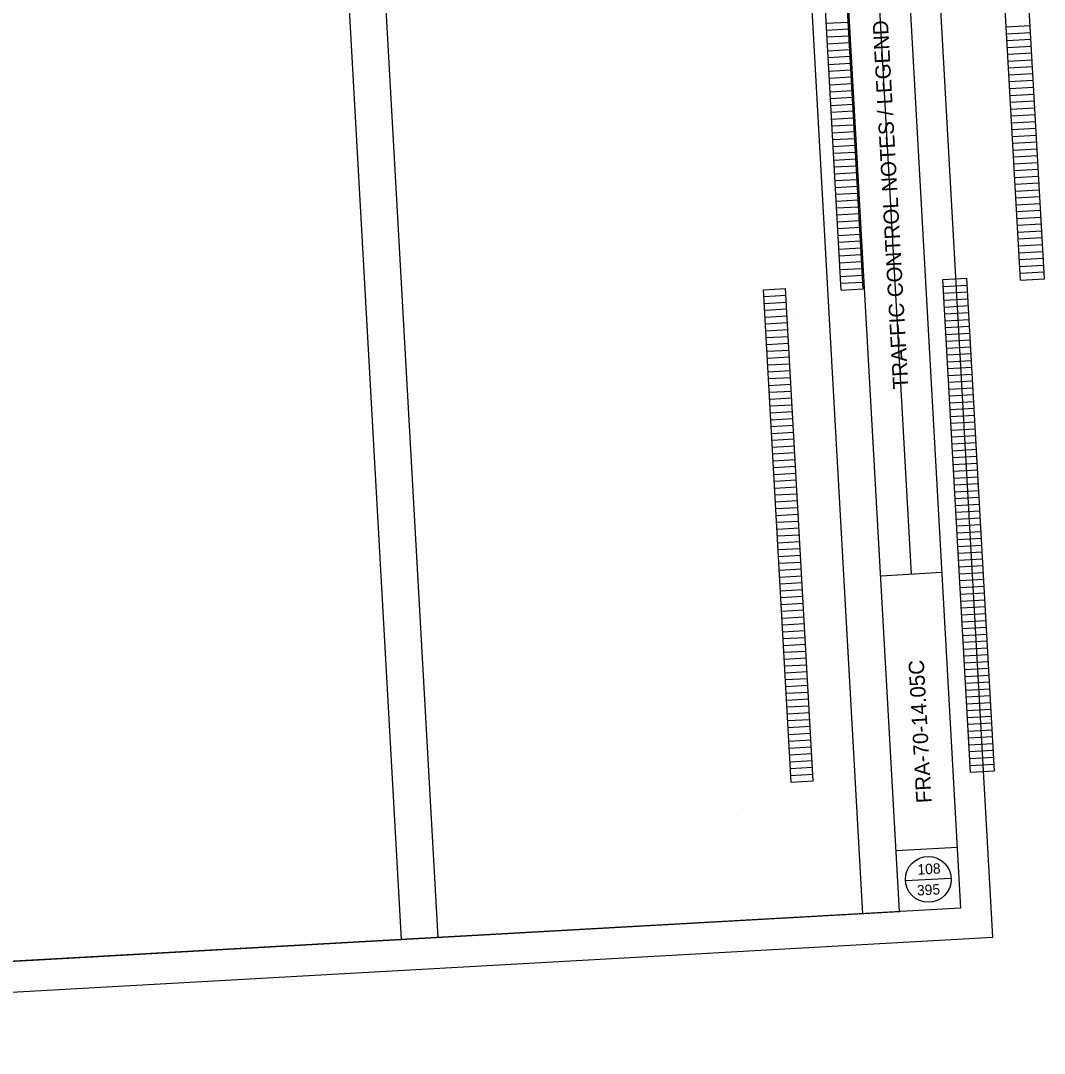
# Model space of a CAD drawing. Extents: x 1822280 to 1825263, y 710141 to 711534.
# Drawn here: x 1823244 to 1824081, y 710141 to 710986 of the extents above; entities that cross this region are included whole.
import ezdxf

# ---------------------------------------------------------------- set-up
doc = ezdxf.new("R2010")
doc.units = 0
for name, color, linetype in [('SC_Scratch1', 7, 'Continuous'), ('SH_Border', 7, 'Continuous'), ('SH_Cut_Line', 7, 'Continuous'), ('SH_Data', 7, 'Continuous'), ('SH_Text', 7, 'Continuous')]:
    doc.layers.add(name, color=color, linetype=linetype)

msp = doc.modelspace()

# ---------------------------------------------------------------- linework, layer by layer
at = {"layer": 'SC_Scratch1'}
for p, q in [((1823932.49, 710255.62), (1823860.99, 711532.17)), ((1823962.45, 710257.29), (1823890.94, 711533.85)), ((1823555.31, 710234.49), (1823483.81, 711511.05)), ((1823585.26, 710236.17), (1823513.76, 711512.73)), ((1823931.48, 711257.13), (1823972.03, 710533.26)), ((1824080.9, 710774.61), (1824058.35, 711177.18)), ((1823914.76, 710765.3), (1823892.21, 711167.87)), ((1823932.73, 710766.31), (1823910.18, 711168.88)), ((1824061.33, 710773.51), (1824038.78, 711176.08)), ((1823902.54, 710983.36), (1823920.52, 710984.37)), ((1823902.86, 710977.77), (1823920.83, 710978.78)), ((1824049.74, 710980.39), (1824069.31, 710981.48)), ((1824050.05, 710974.8), (1824069.62, 710975.89)), ((1823903.17, 710972.18), (1823921.14, 710973.18)), ((1823903.48, 710966.59), (1823921.45, 710967.59)), ((1824050.37, 710969.2), (1824069.94, 710970.3)), ((1823903.8, 710960.99), (1823921.77, 710962)), ((1824050.68, 710963.61), (1824070.25, 710964.71)), ((1824050.99, 710958.02), (1824070.56, 710959.12)), ((1823904.11, 710955.4), (1823922.08, 710956.41)), ((1823904.42, 710949.81), (1823922.39, 710950.82)), ((1824051.31, 710952.43), (1824070.88, 710953.53)), ((1823904.74, 710944.22), (1823922.71, 710945.23)), ((1824051.62, 710946.84), (1824071.19, 710947.94)), ((1824051.93, 710941.25), (1824071.5, 710942.34)), ((1823905.05, 710938.63), (1823923.02, 710939.64)), ((1823905.36, 710933.04), (1823923.33, 710934.05)), ((1824052.25, 710935.66), (1824071.81, 710936.75)), ((1824075.62, 710933.58), (1824075.62, 710933.58)), ((1823905.68, 710927.45), (1823923.65, 710928.45)), ((1824052.56, 710930.07), (1824072.13, 710931.16)), ((1824052.87, 710924.47), (1824072.44, 710925.57)), ((1823905.99, 710921.86), (1823923.96, 710922.86)), ((1823906.3, 710916.26), (1823924.27, 710917.27)), ((1824053.19, 710918.88), (1824072.75, 710919.98)), ((1823906.61, 710910.67), (1823924.59, 710911.68)), ((1823906.93, 710905.08), (1823924.9, 710906.09)), ((1824053.5, 710913.29), (1824073.07, 710914.39)), ((1824053.81, 710907.7), (1824073.38, 710908.8)), ((1823907.24, 710899.49), (1823925.21, 710900.5)), ((1824054.12, 710902.11), (1824073.69, 710903.21)), ((1824054.44, 710896.52), (1824074.01, 710897.61)), ((1823907.55, 710893.9), (1823925.53, 710894.91)), ((1823907.87, 710888.31), (1823925.84, 710889.32)), ((1824054.75, 710890.93), (1824074.32, 710892.02)), ((1823908.18, 710882.72), (1823926.15, 710883.72)), ((1824055.06, 710885.34), (1824074.63, 710886.43)), ((1824055.38, 710879.74), (1824074.95, 710880.84)), ((1823908.49, 710877.13), (1823926.47, 710878.13)), ((1823908.81, 710871.53), (1823926.78, 710872.54)), ((1824055.69, 710874.15), (1824075.26, 710875.25)), ((1823909.12, 710865.94), (1823927.09, 710866.95)), ((1824056, 710868.56), (1824075.57, 710869.66)), ((1824056.32, 710862.97), (1824075.89, 710864.07)), ((1823909.43, 710860.35), (1823927.41, 710861.36)), ((1823909.75, 710854.76), (1823927.72, 710855.77)), ((1824056.63, 710857.38), (1824076.2, 710858.48)), ((1823910.06, 710849.17), (1823928.03, 710850.18)), ((1824056.94, 710851.79), (1824076.51, 710852.88)), ((1824057.26, 710846.2), (1824076.83, 710847.29)), ((1823910.37, 710843.58), (1823928.34, 710844.59)), ((1823910.69, 710837.99), (1823928.66, 710838.99)), ((1824057.57, 710840.61), (1824077.14, 710841.7)), ((1823911, 710832.4), (1823928.97, 710833.4)), ((1824057.88, 710835.01), (1824077.45, 710836.11)), ((1824058.2, 710829.42), (1824077.77, 710830.52)), ((1823911.31, 710826.81), (1823929.28, 710827.81)), ((1823911.63, 710821.21), (1823929.6, 710822.22)), ((1824058.51, 710823.83), (1824078.08, 710824.93)), ((1823911.94, 710815.62), (1823929.91, 710816.63)), ((1824058.82, 710818.24), (1824078.39, 710819.34)), ((1824059.14, 710812.65), (1824078.7, 710813.75)), ((1823912.25, 710810.03), (1823930.22, 710811.04)), ((1823912.57, 710804.44), (1823930.54, 710805.45)), ((1824059.45, 710807.06), (1824079.02, 710808.15)), ((1823912.88, 710798.85), (1823930.85, 710799.86)), ((1824059.76, 710801.47), (1824079.33, 710802.56)), ((1824060.08, 710795.88), (1824079.64, 710796.97)), ((1823913.19, 710793.26), (1823931.16, 710794.26)), ((1823913.5, 710787.67), (1823931.48, 710788.67)), ((1824060.39, 710790.28), (1824079.96, 710791.38)), ((1823913.82, 710782.08), (1823931.79, 710783.08)), ((1824060.7, 710784.69), (1824080.27, 710785.79)), ((1824061.01, 710779.1), (1824080.58, 710780.2)), ((1823914.13, 710776.48), (1823932.1, 710777.49)), ((1823914.44, 710770.89), (1823932.42, 710771.9)), ((1823997.93, 710773.83), (1824017.5, 710774.93)), ((1824020.48, 710371.27), (1823997.93, 710773.83)), ((1824040.05, 710372.36), (1824017.5, 710774.93)), ((1824061.33, 710773.51), (1824080.9, 710774.61)), ((1823851.36, 710765.62), (1823869.33, 710766.63)), ((1823873.91, 710363.06), (1823851.36, 710765.62)), ((1823891.88, 710364.06), (1823869.33, 710766.63)), ((1823914.76, 710765.3), (1823932.73, 710766.31)), ((1823998.24, 710768.24), (1824017.81, 710769.34)), ((1823998.56, 710762.65), (1824018.13, 710763.75)), ((1823851.67, 710760.03), (1823869.65, 710761.04)), ((1823851.99, 710754.44), (1823869.96, 710755.45)), ((1823998.87, 710757.06), (1824018.44, 710758.16)), ((1823852.3, 710748.85), (1823870.27, 710749.86)), ((1823999.18, 710751.47), (1824018.75, 710752.57)), ((1823999.5, 710745.88), (1824019.07, 710746.97)), ((1823852.61, 710743.26), (1823870.58, 710744.27)), ((1823852.93, 710737.67), (1823870.9, 710738.68)), ((1823875.92, 710743.5), (1823875.92, 710743.5)), ((1823999.81, 710740.29), (1824019.38, 710741.38)), ((1823853.24, 710732.08), (1823871.21, 710733.08)), ((1824000.12, 710734.7), (1824019.69, 710735.79)), ((1824000.44, 710729.1), (1824020.01, 710730.2)), ((1823853.55, 710726.49), (1823871.52, 710727.49)), ((1823853.87, 710720.89), (1823871.84, 710721.9)), ((1824000.75, 710723.51), (1824020.32, 710724.61)), ((1823854.18, 710715.3), (1823872.15, 710716.31)), ((1824001.06, 710717.92), (1824020.63, 710719.02)), ((1824001.38, 710712.33), (1824020.94, 710713.43)), ((1823854.49, 710709.71), (1823872.46, 710710.72)), ((1823854.8, 710704.12), (1823872.78, 710705.13)), ((1824001.69, 710706.74), (1824021.26, 710707.84)), ((1823855.12, 710698.53), (1823873.09, 710699.54)), ((1824002, 710701.15), (1824021.57, 710702.24)), ((1824002.31, 710695.56), (1824021.88, 710696.65)), ((1823855.43, 710692.94), (1823873.4, 710693.95)), ((1823855.74, 710687.35), (1823873.72, 710688.35)), ((1824002.63, 710689.97), (1824022.2, 710691.06)), ((1823856.06, 710681.76), (1823874.03, 710682.76)), ((1824002.94, 710684.37), (1824022.51, 710685.47)), ((1824003.25, 710678.78), (1824022.82, 710679.88)), ((1823856.37, 710676.16), (1823874.34, 710677.17)), ((1823856.68, 710670.57), (1823874.66, 710671.58)), ((1824003.57, 710673.19), (1824023.14, 710674.29)), ((1823857, 710664.98), (1823874.97, 710665.99)), ((1824003.88, 710667.6), (1824023.45, 710668.7)), ((1824004.19, 710662.01), (1824023.76, 710663.11)), ((1823857.31, 710659.39), (1823875.28, 710660.4)), ((1823857.62, 710653.8), (1823875.6, 710654.81)), ((1824004.51, 710656.42), (1824024.08, 710657.51)), ((1823857.94, 710648.21), (1823875.91, 710649.22)), ((1824004.82, 710650.83), (1824024.39, 710651.92)), ((1824005.13, 710645.24), (1824024.7, 710646.33)), ((1823858.25, 710642.62), (1823876.22, 710643.62)), ((1823858.56, 710637.03), (1823876.53, 710638.03)), ((1824005.45, 710639.64), (1824025.02, 710640.74)), ((1823858.88, 710631.43), (1823876.85, 710632.44)), ((1824005.76, 710634.05), (1824025.33, 710635.15)), ((1824006.07, 710628.46), (1824025.64, 710629.56)), ((1823859.19, 710625.84), (1823877.16, 710626.85)), ((1823859.5, 710620.25), (1823877.47, 710621.26)), ((1824006.39, 710622.87), (1824025.96, 710623.97)), ((1823859.82, 710614.66), (1823877.79, 710615.67)), ((1824006.7, 710617.28), (1824026.27, 710618.38)), ((1824007.01, 710611.69), (1824026.58, 710612.78)), ((1823860.13, 710609.07), (1823878.1, 710610.08)), ((1823860.44, 710603.48), (1823878.41, 710604.49)), ((1824007.33, 710606.1), (1824026.89, 710607.19)), ((1823860.76, 710597.89), (1823878.73, 710598.89)), ((1824007.64, 710600.51), (1824027.21, 710601.6)), ((1824007.95, 710594.91), (1824027.52, 710596.01)), ((1823861.07, 710592.3), (1823879.04, 710593.3)), ((1823861.38, 710586.71), (1823879.35, 710587.71)), ((1824008.27, 710589.32), (1824027.83, 710590.42)), ((1823861.69, 710581.11), (1823879.67, 710582.12)), ((1824008.58, 710583.73), (1824028.15, 710584.83)), ((1824008.89, 710578.14), (1824028.46, 710579.24)), ((1823862.01, 710575.52), (1823879.98, 710576.53)), ((1823862.32, 710569.93), (1823880.29, 710570.94)), ((1824009.2, 710572.55), (1824028.77, 710573.65)), ((1823862.63, 710564.34), (1823880.61, 710565.35)), ((1824009.52, 710566.96), (1824029.09, 710568.05)), ((1824009.83, 710561.37), (1824029.4, 710562.46)), ((1823862.95, 710558.75), (1823880.92, 710559.76)), ((1823863.26, 710553.16), (1823881.23, 710554.16)), ((1824010.14, 710555.78), (1824029.71, 710556.87)), ((1823863.57, 710547.57), (1823881.55, 710548.57)), ((1824010.46, 710550.18), (1824030.03, 710551.28)), ((1824010.77, 710544.59), (1824030.34, 710545.69)), ((1823863.89, 710541.98), (1823881.86, 710542.98)), ((1823864.2, 710536.38), (1823882.17, 710537.39)), ((1824011.08, 710539), (1824030.65, 710540.1)), ((1823864.51, 710530.79), (1823882.49, 710531.8)), ((1824011.4, 710533.41), (1824030.97, 710534.51)), ((1824011.71, 710527.82), (1824031.28, 710528.92)), ((1823864.83, 710525.2), (1823882.8, 710526.21)), ((1823865.14, 710519.61), (1823883.11, 710520.62)), ((1824012.02, 710522.23), (1824031.59, 710523.32)), ((1823865.45, 710514.02), (1823883.42, 710515.03)), ((1823865.77, 710508.43), (1823883.74, 710509.43)), ((1824012.34, 710516.64), (1824031.91, 710517.73)), ((1824012.65, 710511.05), (1824032.22, 710512.14)), ((1823866.08, 710502.84), (1823884.05, 710503.84)), ((1824012.96, 710505.46), (1824032.53, 710506.55)), ((1824013.28, 710499.86), (1824032.85, 710500.96)), ((1823866.39, 710497.25), (1823884.36, 710498.25)), ((1823866.71, 710491.65), (1823884.68, 710492.66)), ((1824013.59, 710494.27), (1824033.16, 710495.37)), ((1823867.02, 710486.06), (1823884.99, 710487.07)), ((1824013.9, 710488.68), (1824033.47, 710489.78)), ((1824014.22, 710483.09), (1824033.78, 710484.19)), ((1823867.33, 710480.47), (1823885.3, 710481.48)), ((1823867.65, 710474.88), (1823885.62, 710475.89)), ((1824014.53, 710477.5), (1824034.1, 710478.59)), ((1823867.96, 710469.29), (1823885.93, 710470.3)), ((1824014.84, 710471.91), (1824034.41, 710473)), ((1824015.16, 710466.32), (1824034.72, 710467.41)), ((1823868.27, 710463.7), (1823886.24, 710464.7)), ((1823868.58, 710458.11), (1823886.56, 710459.11)), ((1824015.47, 710460.73), (1824035.04, 710461.82)), ((1823868.9, 710452.52), (1823886.87, 710453.52)), ((1824015.78, 710455.13), (1824035.35, 710456.23)), ((1824016.09, 710449.54), (1824035.66, 710450.64)), ((1823869.21, 710446.92), (1823887.18, 710447.93)), ((1823869.52, 710441.33), (1823887.5, 710442.34)), ((1824016.41, 710443.95), (1824035.98, 710445.05)), ((1823869.84, 710435.74), (1823887.81, 710436.75)), ((1824016.72, 710438.36), (1824036.29, 710439.46)), ((1824017.03, 710432.77), (1824036.6, 710433.87)), ((1823870.15, 710430.15), (1823888.12, 710431.16)), ((1823870.46, 710424.56), (1823888.44, 710425.57)), ((1824017.35, 710427.18), (1824036.92, 710428.27)), ((1823870.78, 710418.97), (1823888.75, 710419.97)), ((1824017.66, 710421.59), (1824037.23, 710422.68)), ((1824017.97, 710416), (1824037.54, 710417.09)), ((1823871.09, 710413.38), (1823889.06, 710414.38)), ((1823871.4, 710407.79), (1823889.38, 710408.79)), ((1824018.29, 710410.4), (1824037.86, 710411.5)), ((1823871.72, 710402.19), (1823889.69, 710403.2)), ((1824018.6, 710404.81), (1824038.17, 710405.91)), ((1824018.91, 710399.22), (1824038.48, 710400.32)), ((1823872.03, 710396.6), (1823890, 710397.61)), ((1823872.34, 710391.01), (1823890.31, 710392.02)), ((1824019.23, 710393.63), (1824038.8, 710394.73)), ((1823872.66, 710385.42), (1823890.63, 710386.43)), ((1824019.54, 710388.04), (1824039.11, 710389.14)), ((1824019.85, 710382.45), (1824039.42, 710383.54)), ((1823872.97, 710379.83), (1823890.94, 710380.84)), ((1823873.28, 710374.24), (1823891.25, 710375.24)), ((1824020.17, 710376.86), (1824039.74, 710377.95)), ((1823873.6, 710368.65), (1823891.57, 710369.65)), ((1824020.48, 710371.27), (1824040.05, 710372.36)), ((1823873.91, 710363.06), (1823891.88, 710364.06)), ((1823835.07, 710341.25), (1823835.07, 710341.25))]:
    msp.add_line(p, q, dxfattribs=at)
at = {"layer": 'SH_Border'}
for p, q in [((1823962.45, 710257.29), (1823903.73, 711305.65)), ((1823947.07, 710531.86), (1823996.99, 710534.66)), ((1823959.65, 710307.22), (1824009.57, 710310.01))]:
    msp.add_line(p, q, dxfattribs=at)
msp.add_lwpolyline([(1822381.11, 711220.37), (1823953.65, 711308.45), (1824012.37, 710260.09), (1822439.83, 710172.01)], close=True, dxfattribs=at)
at = {"layer": 'SH_Cut_Line'}
msp.add_lwpolyline([(1822341.39, 710141.46), (1824038.73, 710236.53), (1823977.21, 711334.81), (1822279.87, 711239.73)], close=True, dxfattribs=at)
at = {"layer": 'SH_Data'}
msp.add_line((1823967.29, 710282.6), (1824004.73, 710284.7), dxfattribs=at)
msp.add_circle((1823986.01, 710283.65), 18.75, dxfattribs=at)
at = {"layer": 'SH_Text'}
msp.add_line((1822864.89, 710195.82), (1823962.45, 710257.29), dxfattribs=at)

# ---------------------------------------------------------------- texts
at = {"layer": 'SH_Data'}
for s, height, rotation, p in [('TRAFFIC CONTROL NOTES / LEGEND', 12.5, 93.20591, (1823969.8, 710684.75)), ('FRA-70-14.05C', 12.5, 93.20591, (1823988.76, 710346.37)), ('108', 8.5, 3.20591, (1823977.35, 710287.42)), ('395', 8.5, 3.20591, (1823976.93, 710270.37))]:
    msp.add_text(s, height=height, rotation=rotation, dxfattribs=at).set_placement(p)

doc.saveas('drawing.dxf')
